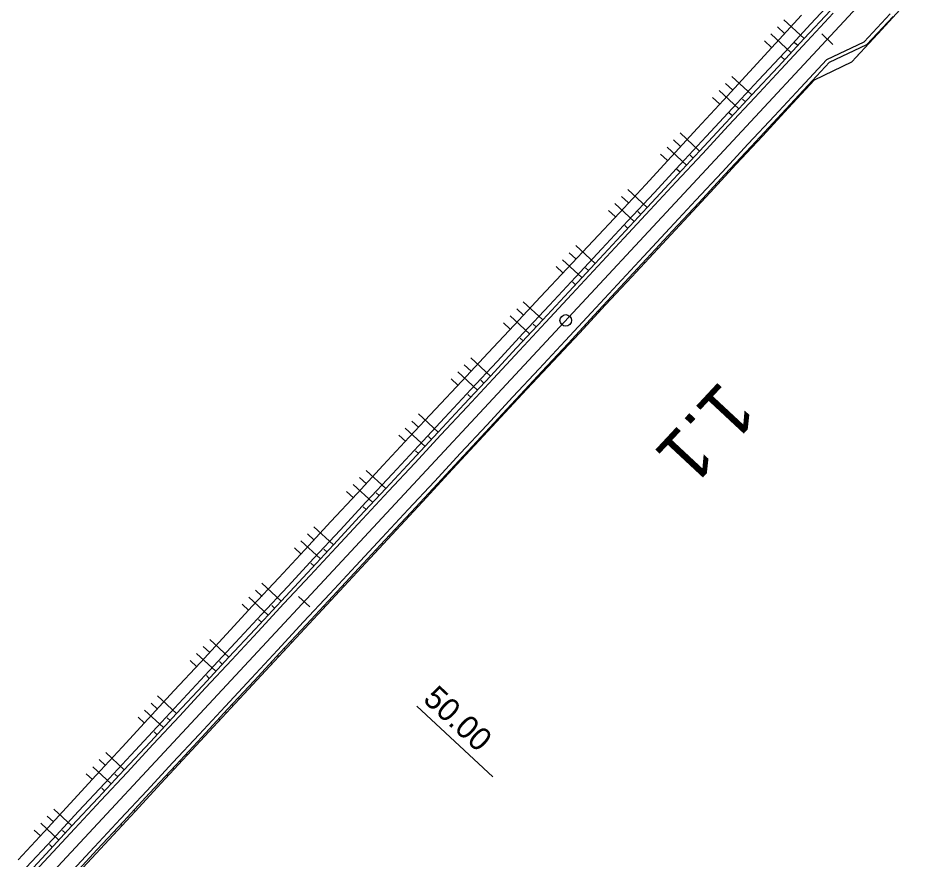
# Model space of a CAD drawing. Extents: x -481645 to -478728, y -1113199 to -1110710.
# Drawn here: x -479232.4 to -479114.8, y -1111049.8 to -1110940.2 of the extents above; entities that cross this region are included whole.
import ezdxf

# ---------------------------------------------------------------- set-up
doc = ezdxf.new("R2010")
doc.units = 0
for name, color, linetype in [('CP14_HATCH_SLOPE_L', 7, 'Continuous'), ('CP1_HECTOMETRY', 7, 'Continuous'), ('O6_HATCH_SLOPE_L', 7, 'Continuous'), ('O6_HATCH_SLOPE_R', 7, 'Continuous'), ('O6_HLBODY', 7, 'Continuous'), ('O6_HRANA_TELESO', 7, 'Continuous'), ('O6_OSA', 7, 'Continuous'), ('O6_VOZOVKA', 7, 'Continuous'), ('O6_ZPEVKRAJ', 7, 'Continuous')]:
    doc.layers.add(name, color=color, linetype=linetype)

msp = doc.modelspace()

# ---------------------------------------------------------------- linework, layer by layer
at = {"layer": 'CP14_HATCH_SLOPE_L'}
for p, q in [((-479120.57, -1110942.18), (-479120.5, -1110942.24)), ((-479121.42, -1110943.09), (-479121.39, -1110943.12)), ((-479121.35, -1110943.16), (-479121.35, -1110943.16)), ((-479122.27, -1110944.01), (-479122.2, -1110944.07)), ((-479123.12, -1110944.92), (-479123.09, -1110944.96)), ((-479123.05, -1110944.99), (-479123.05, -1110944.99)), ((-479128.84, -1110948.14), (-479128.75, -1110948.23)), ((-479129.7, -1110949.05), (-479129.65, -1110949.1)), ((-479129.6, -1110949.14), (-479129.6, -1110949.14)), ((-479130.55, -1110949.97), (-479130.45, -1110950.06)), ((-479131.4, -1110950.88), (-479131.35, -1110950.93)), ((-479131.29, -1110950.98), (-479131.29, -1110950.98)), ((-479136.51, -1110956.38), (-479136.45, -1110956.43)), ((-479135.65, -1110955.46), (-479135.54, -1110955.57)), ((-479137.36, -1110957.29), (-479137.24, -1110957.4)), ((-479136.39, -1110956.49), (-479136.39, -1110956.49)), ((-479138.21, -1110958.21), (-479138.15, -1110958.26)), ((-479138.09, -1110958.32), (-479138.09, -1110958.32)), ((-479142.46, -1110962.78), (-479142.34, -1110962.9)), ((-479144.17, -1110964.61), (-479144.04, -1110964.73)), ((-479143.31, -1110963.7), (-479143.25, -1110963.76)), ((-479143.19, -1110963.82), (-479143.19, -1110963.82)), ((-479145.02, -1110965.53), (-479144.95, -1110965.59)), ((-479144.89, -1110965.65), (-479144.89, -1110965.65)), ((-479149.27, -1110970.11), (-479149.14, -1110970.23)), ((-479150.12, -1110971.02), (-479150.06, -1110971.08)), ((-479149.99, -1110971.14), (-479149.99, -1110971.14)), ((-479151.83, -1110972.85), (-479151.76, -1110972.91)), ((-479150.98, -1110971.94), (-479150.85, -1110972.06)), ((-479151.7, -1110972.97), (-479151.7, -1110972.97)), ((-479156.08, -1110977.43), (-479155.96, -1110977.54)), ((-479156.93, -1110978.34), (-479156.87, -1110978.4)), ((-479156.81, -1110978.46), (-479156.81, -1110978.46)), ((-479157.79, -1110979.26), (-479157.67, -1110979.37)), ((-479158.64, -1110980.18), (-479158.58, -1110980.23)), ((-479158.52, -1110980.28), (-479158.52, -1110980.28)), ((-479163.74, -1110985.67), (-479163.69, -1110985.72)), ((-479163.63, -1110985.77), (-479163.63, -1110985.77)), ((-479162.89, -1110984.75), (-479162.78, -1110984.86)), ((-479164.6, -1110986.58), (-479164.49, -1110986.69)), ((-479165.45, -1110987.5), (-479165.39, -1110987.55)), ((-479165.34, -1110987.6), (-479165.34, -1110987.6)), ((-479169.7, -1110992.07), (-479169.6, -1110992.17)), ((-479171.41, -1110993.91), (-479171.3, -1110994)), ((-479170.55, -1110992.99), (-479170.5, -1110993.04)), ((-479170.45, -1110993.08), (-479170.45, -1110993.08)), ((-479172.26, -1110994.82), (-479172.21, -1110994.87)), ((-479172.16, -1110994.91), (-479172.16, -1110994.91)), ((-479176.51, -1110999.4), (-479176.4, -1110999.51)), ((-479177.36, -1111000.31), (-479177.3, -1111000.37)), ((-479177.24, -1111000.42), (-479177.24, -1111000.42)), ((-479179.07, -1111002.14), (-479179, -1111002.2)), ((-479178.94, -1111002.26), (-479178.94, -1111002.26)), ((-479178.22, -1111001.23), (-479178.09, -1111001.34)), ((-479183.32, -1111006.72), (-479183.19, -1111006.84)), ((-479184.17, -1111007.64), (-479184.11, -1111007.7)), ((-479184.04, -1111007.76), (-479184.04, -1111007.76)), ((-479185.03, -1111008.55), (-479184.89, -1111008.68)), ((-479185.88, -1111009.47), (-479185.81, -1111009.53)), ((-479185.74, -1111009.59), (-479185.74, -1111009.59)), ((-479190.13, -1111014.04), (-479189.99, -1111014.17)), ((-479190.98, -1111014.96), (-479190.91, -1111015.02)), ((-479190.85, -1111015.09), (-479190.85, -1111015.09)), ((-479191.84, -1111015.88), (-479191.7, -1111016)), ((-479192.69, -1111016.79), (-479192.62, -1111016.85)), ((-479192.55, -1111016.92), (-479192.55, -1111016.92)), ((-479197.79, -1111022.28), (-479197.72, -1111022.35)), ((-479196.94, -1111021.37), (-479196.8, -1111021.5)), ((-479198.65, -1111023.2), (-479198.5, -1111023.33)), ((-479197.65, -1111022.42), (-479197.65, -1111022.42)), ((-479199.5, -1111024.11), (-479199.42, -1111024.18)), ((-479199.35, -1111024.25), (-479199.35, -1111024.25)), ((-479203.75, -1111028.69), (-479203.6, -1111028.83)), ((-479205.45, -1111030.52), (-479205.3, -1111030.66)), ((-479204.6, -1111029.6), (-479204.53, -1111029.67)), ((-479204.45, -1111029.74), (-479204.45, -1111029.74)), ((-479206.31, -1111031.44), (-479206.23, -1111031.51)), ((-479206.16, -1111031.57), (-479206.16, -1111031.57)), ((-479210.56, -1111036.01), (-479210.41, -1111036.16)), ((-479211.41, -1111036.93), (-479211.34, -1111037)), ((-479211.26, -1111037.07), (-479211.26, -1111037.07)), ((-479213.12, -1111038.76), (-479213.04, -1111038.83)), ((-479212.26, -1111037.84), (-479212.11, -1111037.99)), ((-479212.96, -1111038.91), (-479212.96, -1111038.91)), ((-479217.37, -1111043.34), (-479217.2, -1111043.49)), ((-479218.22, -1111044.25), (-479218.14, -1111044.33)), ((-479218.05, -1111044.41), (-479218.05, -1111044.41)), ((-479219.07, -1111045.17), (-479218.9, -1111045.33)), ((-479219.92, -1111046.08), (-479219.84, -1111046.16)), ((-479219.75, -1111046.24), (-479219.75, -1111046.24))]:
    msp.add_line(p, q, dxfattribs=at)
at = {"layer": 'CP1_HECTOMETRY'}
msp.add_line((-479231.87, -1111055.62), (-478997.26, -1110803.33), dxfattribs=at)
at = {"layer": 'O6_HATCH_SLOPE_L'}
msp.add_circle((-479161.14, -1110979.56), 0.75, dxfattribs=at)
at = {"layer": 'O6_HATCH_SLOPE_R'}
for p, q in [((-479130.09, -1110942.87), (-479132.73, -1110940.41)), ((-479131.79, -1110944.7), (-479134.43, -1110942.25)), ((-479132.66, -1110942.18), (-479133.58, -1110941.33)), ((-479134.36, -1110944.02), (-479135.27, -1110943.17)), ((-479130.94, -1110943.78), (-479131.34, -1110943.41)), ((-479132.64, -1110945.62), (-479133.05, -1110945.24)), ((-479136.9, -1110950.19), (-479139.5, -1110947.78)), ((-479139.45, -1110949.53), (-479140.34, -1110948.7)), ((-479141.14, -1110951.37), (-479142.04, -1110950.54)), ((-479138.6, -1110952.02), (-479141.19, -1110949.62)), ((-479137.75, -1110951.11), (-479138.15, -1110950.74)), ((-479139.45, -1110952.94), (-479139.85, -1110952.57)), ((-479143.71, -1110957.52), (-479146.26, -1110955.14)), ((-479146.23, -1110956.88), (-479147.11, -1110956.06)), ((-479145.41, -1110959.35), (-479147.95, -1110956.98)), ((-479147.93, -1110958.71), (-479148.8, -1110957.91)), ((-479144.56, -1110958.43), (-479144.96, -1110958.06)), ((-479146.26, -1110960.26), (-479146.66, -1110959.89)), ((-479153.02, -1110964.22), (-479153.88, -1110963.42)), ((-479150.52, -1110964.84), (-479153.04, -1110962.5)), ((-479152.22, -1110966.67), (-479154.73, -1110964.33)), ((-479154.72, -1110966.05), (-479155.58, -1110965.25)), ((-479151.37, -1110965.75), (-479151.77, -1110965.39)), ((-479153.07, -1110967.58), (-479153.47, -1110967.22)), ((-479157.33, -1110972.16), (-479159.84, -1110969.82)), ((-479159.03, -1110973.99), (-479161.55, -1110971.65)), ((-479159.83, -1110971.54), (-479160.7, -1110970.74)), ((-479161.54, -1110973.37), (-479162.4, -1110972.56)), ((-479158.18, -1110973.08), (-479158.58, -1110972.71)), ((-479159.88, -1110974.91), (-479160.28, -1110974.54)), ((-479164.14, -1110979.49), (-479166.67, -1110977.13)), ((-479166.65, -1110978.86), (-479167.53, -1110978.04)), ((-479168.36, -1110980.68), (-479169.23, -1110979.87)), ((-479165.84, -1110981.31), (-479168.38, -1110978.96)), ((-479164.99, -1110980.4), (-479165.38, -1110980.03)), ((-479166.69, -1110982.23), (-479167.09, -1110981.87)), ((-479170.95, -1110986.81), (-479173.5, -1110984.44)), ((-479173.47, -1110986.17), (-479174.35, -1110985.35)), ((-479172.65, -1110988.64), (-479175.21, -1110986.26)), ((-479175.17, -1110988), (-479176.06, -1110987.18)), ((-479171.8, -1110987.72), (-479172.19, -1110987.36)), ((-479173.5, -1110989.55), (-479173.89, -1110989.19)), ((-479177.76, -1110994.13), (-479180.33, -1110991.74)), ((-479180.28, -1110993.49), (-479181.18, -1110992.66)), ((-479179.46, -1110995.96), (-479182.03, -1110993.58)), ((-479181.98, -1110995.32), (-479182.88, -1110994.49)), ((-479178.61, -1110995.05), (-479179, -1110994.68)), ((-479180.31, -1110996.88), (-479180.7, -1110996.52)), ((-479184.57, -1111001.45), (-479187.12, -1110999.08)), ((-479186.27, -1111003.28), (-479188.82, -1111000.91)), ((-479187.09, -1111000.82), (-479187.97, -1111000)), ((-479188.78, -1111002.66), (-479189.67, -1111001.83)), ((-479185.42, -1111002.37), (-479185.81, -1111002.01)), ((-479187.12, -1111004.2), (-479187.51, -1111003.84)), ((-479191.38, -1111008.78), (-479193.92, -1111006.42)), ((-479193.88, -1111008.16), (-479194.76, -1111007.34)), ((-479195.58, -1111009.99), (-479196.46, -1111009.17)), ((-479193.08, -1111010.61), (-479195.61, -1111008.25)), ((-479192.23, -1111009.69), (-479192.62, -1111009.33)), ((-479193.93, -1111011.52), (-479194.32, -1111011.16)), ((-479198.19, -1111016.1), (-479200.7, -1111013.76)), ((-479200.68, -1111015.49), (-479201.55, -1111014.68)), ((-479199.89, -1111017.93), (-479202.4, -1111015.6)), ((-479202.38, -1111017.32), (-479203.25, -1111016.52)), ((-479199.04, -1111017.02), (-479199.42, -1111016.66)), ((-479200.74, -1111018.85), (-479201.13, -1111018.49)), ((-479205, -1111023.42), (-479207.49, -1111021.1)), ((-479207.48, -1111022.82), (-479208.34, -1111022.02)), ((-479206.7, -1111025.25), (-479209.19, -1111022.94)), ((-479209.18, -1111024.66), (-479210.04, -1111023.86)), ((-479205.85, -1111024.34), (-479206.23, -1111023.98)), ((-479207.55, -1111026.17), (-479207.93, -1111025.81)), ((-479214.27, -1111030.17), (-479215.12, -1111029.38)), ((-479211.81, -1111030.75), (-479214.27, -1111028.46)), ((-479213.51, -1111032.58), (-479215.96, -1111030.3)), ((-479215.96, -1111032), (-479216.8, -1111031.22)), ((-479212.66, -1111031.66), (-479213.04, -1111031.31)), ((-479214.36, -1111033.49), (-479214.74, -1111033.14)), ((-479218.62, -1111038.07), (-479221.03, -1111035.83)), ((-479221.05, -1111037.52), (-479221.87, -1111036.75)), ((-479222.75, -1111039.35), (-479223.56, -1111038.59)), ((-479220.32, -1111039.9), (-479222.72, -1111037.67)), ((-479219.47, -1111038.98), (-479219.85, -1111038.63)), ((-479221.17, -1111040.81), (-479221.55, -1111040.46)), ((-479225.43, -1111045.39), (-479227.79, -1111043.19)), ((-479227.84, -1111044.86), (-479228.64, -1111044.11)), ((-479227.13, -1111047.22), (-479229.49, -1111045.03)), ((-479229.53, -1111046.69), (-479230.33, -1111045.95)), ((-479226.28, -1111046.31), (-479226.66, -1111045.96)), ((-479227.98, -1111048.14), (-479228.36, -1111047.79))]:
    msp.add_line(p, q, dxfattribs=at)
at = {"layer": 'O6_HLBODY'}
for p, q in [((-479126.35, -1110943.62), (-479127.82, -1110942.26)), ((-479194.45, -1111016.85), (-479195.92, -1111015.49)), ((-479180.54, -1111029.79), (-479170.65, -1111038.99))]:
    msp.add_line(p, q, dxfattribs=at)
at = {"layer": 'O6_HRANA_TELESO'}
for p, q in [((-479129.23, -1110940.95), (-479125.83, -1110937.29)), ((-479132.63, -1110944.62), (-479129.23, -1110940.95)), ((-479136.03, -1110948.28), (-479132.63, -1110944.62)), ((-479139.44, -1110951.94), (-479136.03, -1110948.28)), ((-479142.84, -1110955.6), (-479139.44, -1110951.94)), ((-479146.25, -1110959.27), (-479142.84, -1110955.6)), ((-479149.65, -1110962.93), (-479146.25, -1110959.27)), ((-479153.06, -1110966.59), (-479149.65, -1110962.93)), ((-479156.46, -1110970.25), (-479153.06, -1110966.59)), ((-479159.87, -1110973.91), (-479156.46, -1110970.25)), ((-479163.27, -1110977.57), (-479159.87, -1110973.91)), ((-479166.68, -1110981.23), (-479163.27, -1110977.57)), ((-479170.08, -1110984.9), (-479166.68, -1110981.23)), ((-479173.49, -1110988.56), (-479170.08, -1110984.9)), ((-479176.89, -1110992.22), (-479173.49, -1110988.56)), ((-479180.3, -1110995.88), (-479176.89, -1110992.22)), ((-479183.7, -1110999.54), (-479180.3, -1110995.88)), ((-479187.11, -1111003.2), (-479183.7, -1110999.54)), ((-479190.51, -1111006.86), (-479187.11, -1111003.2)), ((-479193.92, -1111010.52), (-479190.51, -1111006.86)), ((-479197.32, -1111014.19), (-479193.92, -1111010.52)), ((-479200.73, -1111017.85), (-479197.32, -1111014.19)), ((-479204.13, -1111021.51), (-479200.73, -1111017.85)), ((-479207.54, -1111025.17), (-479204.13, -1111021.51)), ((-479210.94, -1111028.83), (-479207.54, -1111025.17)), ((-479214.35, -1111032.49), (-479210.94, -1111028.83)), ((-479217.75, -1111036.16), (-479214.35, -1111032.49)), ((-479221.16, -1111039.82), (-479217.75, -1111036.16)), ((-479224.56, -1111043.48), (-479221.16, -1111039.82)), ((-479227.97, -1111047.14), (-479224.56, -1111043.48)), ((-479231.37, -1111050.8), (-479227.97, -1111047.14))]:
    msp.add_line(p, q, dxfattribs=at)
at = {"layer": 'O6_OSA'}
for p, q in [((-479120.5, -1110942.24), (-479117.11, -1110938.57)), ((-479133.82, -1110943.51), (-479130.46, -1110939.81)), ((-479123.9, -1110945.91), (-479120.5, -1110942.24)), ((-479137.21, -1110947.19), (-479133.82, -1110943.51)), ((-479128.75, -1110948.23), (-479123.9, -1110945.91)), ((-479140.6, -1110950.86), (-479137.21, -1110947.19)), ((-479132.14, -1110951.9), (-479128.75, -1110948.23)), ((-479143.98, -1110954.54), (-479140.6, -1110950.86)), ((-479135.54, -1110955.57), (-479132.14, -1110951.9)), ((-479147.37, -1110958.22), (-479143.98, -1110954.54)), ((-479138.94, -1110959.23), (-479135.54, -1110955.57)), ((-479150.76, -1110961.89), (-479147.37, -1110958.22)), ((-479142.34, -1110962.9), (-479138.94, -1110959.23)), ((-479154.16, -1110965.56), (-479150.76, -1110961.89)), ((-479145.74, -1110966.57), (-479142.34, -1110962.9)), ((-479157.58, -1110969.21), (-479154.16, -1110965.56)), ((-479149.14, -1110970.23), (-479145.74, -1110966.57)), ((-479161, -1110972.86), (-479157.58, -1110969.21)), ((-479152.55, -1110973.89), (-479149.14, -1110970.23)), ((-479164.42, -1110976.51), (-479161, -1110972.86)), ((-479155.96, -1110977.54), (-479152.55, -1110973.89)), ((-479167.84, -1110980.16), (-479164.42, -1110976.51)), ((-479159.37, -1110981.2), (-479155.96, -1110977.54)), ((-479171.25, -1110983.8), (-479167.84, -1110980.16)), ((-479162.78, -1110984.86), (-479159.37, -1110981.2)), ((-479174.67, -1110987.45), (-479171.25, -1110983.8)), ((-479166.19, -1110988.51), (-479162.78, -1110984.86)), ((-479178.09, -1110991.1), (-479174.67, -1110987.45)), ((-479169.6, -1110992.17), (-479166.19, -1110988.51)), ((-479181.51, -1110994.75), (-479178.09, -1110991.1)), ((-479173.01, -1110995.83), (-479169.6, -1110992.17)), ((-479184.91, -1110998.42), (-479181.51, -1110994.75)), ((-479176.4, -1110999.51), (-479173.01, -1110995.83)), ((-479188.31, -1111002.08), (-479184.91, -1110998.42)), ((-479179.79, -1111003.18), (-479176.4, -1110999.51)), ((-479191.71, -1111005.75), (-479188.31, -1111002.08)), ((-479183.19, -1111006.84), (-479179.79, -1111003.18)), ((-479195.11, -1111009.41), (-479191.71, -1111005.75)), ((-479186.59, -1111010.51), (-479183.19, -1111006.84)), ((-479198.51, -1111013.08), (-479195.11, -1111009.41)), ((-479189.99, -1111014.17), (-479186.59, -1111010.51)), ((-479201.91, -1111016.74), (-479198.51, -1111013.08)), ((-479193.4, -1111017.84), (-479189.99, -1111014.17)), ((-479205.31, -1111020.41), (-479201.91, -1111016.74)), ((-479196.8, -1111021.5), (-479193.4, -1111017.84)), ((-479208.71, -1111024.08), (-479205.31, -1111020.41)), ((-479200.2, -1111025.16), (-479196.8, -1111021.5)), ((-479212.11, -1111027.74), (-479208.71, -1111024.08)), ((-479203.6, -1111028.83), (-479200.2, -1111025.16)), ((-479215.5, -1111031.42), (-479212.11, -1111027.74)), ((-479207.01, -1111032.49), (-479203.6, -1111028.83)), ((-479218.88, -1111035.11), (-479215.5, -1111031.42)), ((-479210.41, -1111036.16), (-479207.01, -1111032.49)), ((-479222.27, -1111038.78), (-479218.88, -1111035.11)), ((-479213.81, -1111039.82), (-479210.41, -1111036.16)), ((-479225.66, -1111042.46), (-479222.27, -1111038.78)), ((-479217.2, -1111043.49), (-479213.81, -1111039.82)), ((-479229.05, -1111046.13), (-479225.66, -1111042.46)), ((-479220.6, -1111047.16), (-479217.2, -1111043.49)), ((-479232.44, -1111049.81), (-479229.05, -1111046.13)), ((-479224, -1111050.83), (-479220.6, -1111047.16))]:
    msp.add_line(p, q, dxfattribs=at)
at = {"layer": 'O6_VOZOVKA'}
for p, q in [((-479129.72, -1110943.21), (-479126.32, -1110939.55)), ((-479122.29, -1110943.29), (-479118.89, -1110939.63)), ((-479133.13, -1110946.87), (-479129.72, -1110943.21)), ((-479127.16, -1110945.59), (-479122.29, -1110943.29)), ((-479130.57, -1110949.26), (-479127.16, -1110945.59)), ((-479136.53, -1110950.53), (-479133.13, -1110946.87)), ((-479133.97, -1110952.92), (-479130.57, -1110949.26)), ((-479139.94, -1110954.2), (-479136.53, -1110950.53)), ((-479137.38, -1110956.58), (-479133.97, -1110952.92)), ((-479143.34, -1110957.86), (-479139.94, -1110954.2)), ((-479140.78, -1110960.24), (-479137.38, -1110956.58)), ((-479146.75, -1110961.52), (-479143.34, -1110957.86)), ((-479144.19, -1110963.9), (-479140.78, -1110960.24)), ((-479150.15, -1110965.18), (-479146.75, -1110961.52)), ((-479147.59, -1110967.56), (-479144.19, -1110963.9)), ((-479153.56, -1110968.84), (-479150.15, -1110965.18)), ((-479151, -1110971.22), (-479147.59, -1110967.56)), ((-479156.96, -1110972.5), (-479153.56, -1110968.84)), ((-479154.4, -1110974.89), (-479151, -1110971.22)), ((-479160.37, -1110976.16), (-479156.96, -1110972.5)), ((-479157.81, -1110978.55), (-479154.4, -1110974.89)), ((-479163.77, -1110979.82), (-479160.37, -1110976.16)), ((-479161.21, -1110982.21), (-479157.81, -1110978.55)), ((-479167.18, -1110983.49), (-479163.77, -1110979.82)), ((-479164.61, -1110985.87), (-479161.21, -1110982.21)), ((-479170.58, -1110987.15), (-479167.18, -1110983.49)), ((-479168.02, -1110989.53), (-479164.61, -1110985.87)), ((-479173.99, -1110990.81), (-479170.58, -1110987.15)), ((-479171.42, -1110993.19), (-479168.02, -1110989.53)), ((-479177.39, -1110994.47), (-479173.99, -1110990.81)), ((-479174.83, -1110996.85), (-479171.42, -1110993.19)), ((-479180.8, -1110998.13), (-479177.39, -1110994.47)), ((-479178.23, -1111000.52), (-479174.83, -1110996.85)), ((-479184.2, -1111001.79), (-479180.8, -1110998.13)), ((-479181.64, -1111004.18), (-479178.23, -1111000.52)), ((-479187.61, -1111005.46), (-479184.2, -1111001.79)), ((-479185.04, -1111007.84), (-479181.64, -1111004.18)), ((-479191.01, -1111009.12), (-479187.61, -1111005.46)), ((-479188.45, -1111011.5), (-479185.04, -1111007.84)), ((-479194.42, -1111012.78), (-479191.01, -1111009.12)), ((-479191.85, -1111015.16), (-479188.45, -1111011.5)), ((-479197.82, -1111016.44), (-479194.42, -1111012.78)), ((-479195.26, -1111018.82), (-479191.85, -1111015.16)), ((-479201.23, -1111020.1), (-479197.82, -1111016.44)), ((-479198.67, -1111022.49), (-479195.26, -1111018.82)), ((-479204.63, -1111023.76), (-479201.23, -1111020.1)), ((-479202.07, -1111026.15), (-479198.67, -1111022.49)), ((-479208.04, -1111027.42), (-479204.63, -1111023.76)), ((-479205.48, -1111029.81), (-479202.07, -1111026.15)), ((-479211.44, -1111031.09), (-479208.04, -1111027.42)), ((-479208.88, -1111033.47), (-479205.48, -1111029.81)), ((-479214.85, -1111034.75), (-479211.44, -1111031.09)), ((-479212.28, -1111037.13), (-479208.88, -1111033.47)), ((-479218.25, -1111038.41), (-479214.85, -1111034.75)), ((-479215.69, -1111040.79), (-479212.28, -1111037.13)), ((-479221.66, -1111042.07), (-479218.25, -1111038.41)), ((-479219.09, -1111044.45), (-479215.69, -1111040.79)), ((-479225.06, -1111045.73), (-479221.66, -1111042.07)), ((-479222.5, -1111048.11), (-479219.09, -1111044.45)), ((-479228.47, -1111049.39), (-479225.06, -1111045.73)), ((-479225.9, -1111051.78), (-479222.5, -1111048.11)), ((-479231.87, -1111053.05), (-479228.47, -1111049.39))]:
    msp.add_line(p, q, dxfattribs=at)
at = {"layer": 'O6_ZPEVKRAJ'}
for p, q in [((-479130.09, -1110942.87), (-479126.69, -1110939.21)), ((-479121.93, -1110943.64), (-479118.52, -1110939.97)), ((-479133.49, -1110946.53), (-479130.09, -1110942.87)), ((-479126.79, -1110945.93), (-479121.93, -1110943.64)), ((-479136.9, -1110950.19), (-479133.49, -1110946.53)), ((-479130.2, -1110949.6), (-479126.79, -1110945.93)), ((-479140.3, -1110953.85), (-479136.9, -1110950.19)), ((-479133.6, -1110953.26), (-479130.2, -1110949.6)), ((-479143.71, -1110957.52), (-479140.3, -1110953.85)), ((-479137.01, -1110956.92), (-479133.6, -1110953.26)), ((-479147.11, -1110961.18), (-479143.71, -1110957.52)), ((-479140.42, -1110960.58), (-479137.01, -1110956.92)), ((-479143.82, -1110964.24), (-479140.42, -1110960.58)), ((-479150.52, -1110964.84), (-479147.11, -1110961.18)), ((-479147.23, -1110967.9), (-479143.82, -1110964.24)), ((-479153.92, -1110968.5), (-479150.52, -1110964.84)), ((-479150.63, -1110971.56), (-479147.23, -1110967.9)), ((-479157.33, -1110972.16), (-479153.92, -1110968.5)), ((-479154.04, -1110975.23), (-479150.63, -1110971.56)), ((-479160.73, -1110975.82), (-479157.33, -1110972.16)), ((-479157.44, -1110978.89), (-479154.04, -1110975.23)), ((-479164.14, -1110979.49), (-479160.73, -1110975.82)), ((-479167.54, -1110983.15), (-479164.14, -1110979.49)), ((-479160.84, -1110982.55), (-479157.44, -1110978.89)), ((-479170.95, -1110986.81), (-479167.54, -1110983.15)), ((-479164.25, -1110986.21), (-479160.84, -1110982.55)), ((-479174.35, -1110990.47), (-479170.95, -1110986.81)), ((-479167.65, -1110989.87), (-479164.25, -1110986.21)), ((-479177.76, -1110994.13), (-479174.35, -1110990.47)), ((-479171.06, -1110993.53), (-479167.65, -1110989.87)), ((-479174.46, -1110997.2), (-479171.06, -1110993.53)), ((-479181.16, -1110997.79), (-479177.76, -1110994.13)), ((-479177.87, -1111000.86), (-479174.46, -1110997.2)), ((-479184.57, -1111001.45), (-479181.16, -1110997.79)), ((-479181.27, -1111004.52), (-479177.87, -1111000.86)), ((-479187.97, -1111005.11), (-479184.57, -1111001.45)), ((-479184.68, -1111008.18), (-479181.27, -1111004.52)), ((-479191.38, -1111008.78), (-479187.97, -1111005.11)), ((-479188.08, -1111011.84), (-479184.68, -1111008.18)), ((-479194.78, -1111012.44), (-479191.38, -1111008.78)), ((-479198.19, -1111016.1), (-479194.78, -1111012.44)), ((-479191.49, -1111015.5), (-479188.08, -1111011.84)), ((-479201.59, -1111019.76), (-479198.19, -1111016.1)), ((-479194.89, -1111019.16), (-479191.49, -1111015.5)), ((-479205, -1111023.42), (-479201.59, -1111019.76)), ((-479198.3, -1111022.82), (-479194.89, -1111019.16)), ((-479208.4, -1111027.08), (-479205, -1111023.42)), ((-479201.7, -1111026.49), (-479198.3, -1111022.82)), ((-479205.11, -1111030.15), (-479201.7, -1111026.49)), ((-479211.81, -1111030.75), (-479208.4, -1111027.08)), ((-479208.51, -1111033.81), (-479205.11, -1111030.15)), ((-479215.21, -1111034.41), (-479211.81, -1111030.75)), ((-479211.92, -1111037.47), (-479208.51, -1111033.81)), ((-479218.62, -1111038.07), (-479215.21, -1111034.41)), ((-479215.32, -1111041.13), (-479211.92, -1111037.47)), ((-479222.02, -1111041.73), (-479218.62, -1111038.07)), ((-479218.73, -1111044.79), (-479215.32, -1111041.13)), ((-479225.43, -1111045.39), (-479222.02, -1111041.73)), ((-479228.83, -1111049.05), (-479225.43, -1111045.39)), ((-479222.13, -1111048.46), (-479218.73, -1111044.79)), ((-479232.24, -1111052.71), (-479228.83, -1111049.05)), ((-479225.54, -1111052.12), (-479222.13, -1111048.46))]:
    msp.add_line(p, q, dxfattribs=at)

# ---------------------------------------------------------------- texts
at = {"layer": 'O6_HATCH_SLOPE_L'}
msp.add_text('1.1', height=7, rotation=227.0337, dxfattribs=at).set_placement((-479140.92, -1110987.2))
at = {"layer": 'O6_HLBODY'}
msp.add_text('50.00', height=2.999, rotation=317.0793, dxfattribs=at).set_placement((-479179.86, -1111029.06))

doc.saveas('drawing.dxf')
